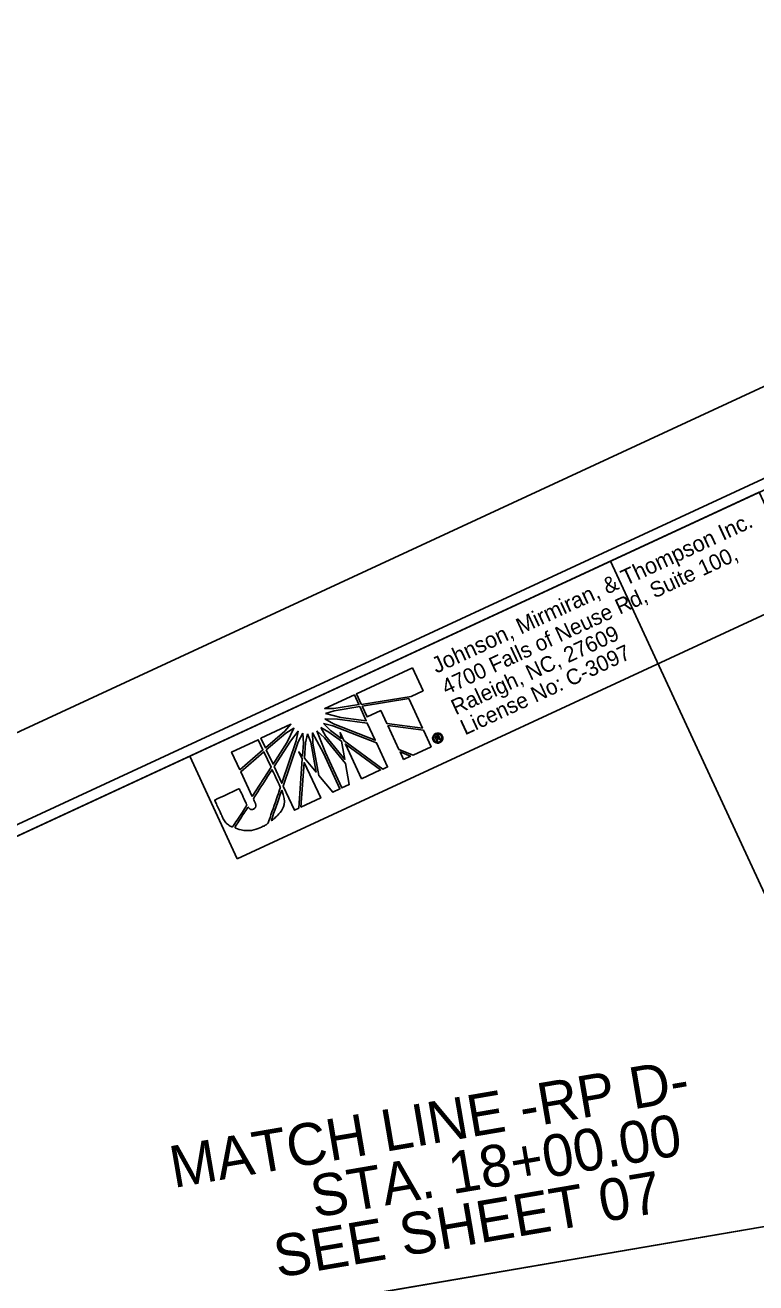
# Model space of a CAD drawing. Extents: x 1722892 to 1724880, y 971019 to 972720.
# Drawn here: x 1724056.8 to 1724231.4, y 972419.6 to 972720.2 of the extents above; entities that cross this region are included whole.
import ezdxf

# ---------------------------------------------------------------- set-up
doc = ezdxf.new("R2010")
doc.units = 0
for name, color, linetype in [('Matchline', 7, 'Continuous'), ('Matchline Text', 7, 'Continuous'), ('Prop Dimension Text', 7, 'Continuous'), ('Sheet Clip Boundary CELL', 7, 'Continuous'), ('Sheet Layout Plan Border', 7, 'Continuous'), ('Sheet Plan CELL', 7, 'Continuous'), ('Sheet Plot Border Inside CELL', 7, 'Continuous'), ('Sheet Plot Border Outside CELL', 7, 'Continuous')]:
    doc.layers.add(name, color=color, linetype=linetype)

msp = doc.modelspace()

# ---------------------------------------------------------------- linework, layer by layer
at = {"layer": 'Matchline'}
msp.add_line((1724068.11, 972404.72), (1724340.27, 972451.29), dxfattribs=at)
at = {"layer": 'Prop Dimension Text'}
for p, q in [((1724149.33, 972566.59), (1724135.95, 972560.37)), ((1724151.88, 972561.11), (1724149.33, 972566.59)), ((1724135.47, 972560.11), (1724128.39, 972556.86)), ((1724136.53, 972557.82), (1724135.47, 972560.11)), ((1724135.95, 972560.37), (1724137.09, 972557.91)), ((1724137.12, 972557.84), (1724149.04, 972559.78)), ((1724148.47, 972559.23), (1724137.3, 972557.46)), ((1724151.74, 972552.2), (1724148.47, 972559.23)), ((1724149.04, 972559.78), (1724151.88, 972561.11)), ((1724128.39, 972556.86), (1724130.57, 972556.85)), ((1724130.61, 972556.31), (1724128.53, 972555.64)), ((1724128.53, 972555.64), (1724132.21, 972554.7)), ((1724130.57, 972556.85), (1724136.53, 972557.82)), ((1724136.76, 972557.34), (1724130.61, 972556.31)), ((1724138.28, 972553.94), (1724136.76, 972557.34)), ((1724137.09, 972557.91), (1724137.12, 972557.84)), ((1724137.3, 972557.46), (1724137.32, 972557.42)), ((1724137.32, 972557.42), (1724138.51, 972554.85)), ((1724138.51, 972554.85), (1724141.78, 972556.37)), ((1724141.78, 972556.37), (1724143.2, 972553.32)), ((1724120.28, 972553.09), (1724113.12, 972549.76)), ((1724118.83, 972551.43), (1724120.28, 972553.09)), ((1724128.04, 972553.28), (1724129.76, 972551.61)), ((1724130.33, 972552.77), (1724128.04, 972553.28)), ((1724128.43, 972554.4), (1724130.47, 972553.21)), ((1724131.46, 972554.31), (1724128.43, 972554.4)), ((1724140.75, 972548.64), (1724130.33, 972552.77)), ((1724130.47, 972553.21), (1724140.44, 972549.3)), ((1724138.55, 972553.38), (1724131.46, 972554.31)), ((1724132.21, 972554.7), (1724138.28, 972553.94)), ((1724140.44, 972549.3), (1724138.55, 972553.38)), ((1724143.2, 972553.32), (1724151.74, 972552.2)), ((1724143.44, 972552.79), (1724146.09, 972547.1)), ((1724151.97, 972551.71), (1724143.44, 972552.79)), ((1724112.47, 972549.42), (1724106.1, 972546.47)), ((1724113.61, 972546.97), (1724112.47, 972549.42)), ((1724113.12, 972549.76), (1724114.18, 972547.48)), ((1724114.18, 972547.48), (1724118.83, 972551.43)), ((1724119.06, 972550.94), (1724114.41, 972546.99)), ((1724121.02, 972552.16), (1724119.06, 972550.94)), ((1724119.38, 972548.79), (1724121.02, 972552.16)), ((1724122.01, 972551.42), (1724120.15, 972549.06)), ((1724121.58, 972549.12), (1724122.01, 972551.42)), ((1724123.1, 972550.99), (1724122.01, 972548.9)), ((1724123.27, 972548.59), (1724123.1, 972550.99)), ((1724124.28, 972550.85), (1724123.77, 972548.64)), ((1724125.01, 972548.8), (1724124.28, 972550.85)), ((1724128.07, 972546.16), (1724125.46, 972551.05)), ((1724125.46, 972551.05), (1724125.53, 972548.61)), ((1724126.51, 972551.54), (1724128.52, 972546.37)), ((1724128.3, 972549.89), (1724126.51, 972551.54)), ((1724127.4, 972552.3), (1724128.55, 972550.36)), ((1724129.38, 972551.25), (1724127.4, 972552.3)), ((1724133.37, 972543.75), (1724128.3, 972549.89)), ((1724128.55, 972550.36), (1724133.19, 972544.69)), ((1724132.41, 972549.03), (1724129.38, 972551.25)), ((1724129.76, 972551.61), (1724132.3, 972549.71)), ((1724132.3, 972549.71), (1724132.04, 972551.12)), ((1724132.04, 972551.12), (1724132.91, 972549.26)), ((1724153.81, 972547.75), (1724151.97, 972551.71)), ((1724154.75, 972550.11), (1724155.15, 972550.29)), ((1724155.2, 972549.13), (1724154.75, 972550.11)), ((1724154.88, 972550.87), (1724154.98, 972550.66)), ((1724154.98, 972550.66), (1724154.88, 972550.87)), ((1724155.24, 972550.11), (1724155.06, 972550.03)), ((1724155.06, 972550.03), (1724155.17, 972549.8)), ((1724155.15, 972550.29), (1724155.21, 972550.32)), ((1724155.15, 972550.29), (1724155.24, 972550.11)), ((1724155.24, 972550.11), (1724155.15, 972550.29)), ((1724155.17, 972549.8), (1724155.34, 972549.88)), ((1724155.26, 972550.12), (1724155.24, 972550.11)), ((1724155.42, 972549.7), (1724155.25, 972549.62)), ((1724155.25, 972549.62), (1724155.42, 972549.24)), ((1724155.34, 972549.88), (1724155.42, 972549.7)), ((1724155.42, 972549.7), (1724155.34, 972549.88)), ((1724155.34, 972549.88), (1724155.35, 972549.88)), ((1724155.43, 972549.7), (1724155.42, 972549.7)), ((1724106.1, 972546.47), (1724108.06, 972542.24)), ((1724108.06, 972542.24), (1724113.61, 972546.97)), ((1724113.83, 972546.5), (1724108.29, 972541.76)), ((1724115.54, 972542.82), (1724113.83, 972546.5)), ((1724114.41, 972546.99), (1724116.01, 972543.54)), ((1724116.01, 972543.54), (1724119.38, 972548.79)), ((1724120.15, 972549.06), (1724116.27, 972542.99)), ((1724118.11, 972539.01), (1724121.58, 972549.12)), ((1724122.01, 972548.9), (1724118.42, 972538.34)), ((1724122.99, 972544.87), (1724122.21, 972546.55)), ((1724122.21, 972546.55), (1724123.06, 972545.54)), ((1724123.06, 972545.54), (1724123.27, 972548.59)), ((1724123.77, 972548.64), (1724123.52, 972545.03)), ((1724126.31, 972541.68), (1724125.01, 972548.8)), ((1724125.53, 972548.61), (1724126.93, 972540.89)), ((1724133.19, 972544.69), (1724132.41, 972549.03)), ((1724132.91, 972549.26), (1724142.28, 972542.4)), ((1724141.74, 972542.19), (1724133.33, 972548.35)), ((1724133.33, 972548.35), (1724137.18, 972540.07)), ((1724143.4, 972542.92), (1724140.75, 972548.64)), ((1724146.09, 972547.1), (1724149.49, 972545.75)), ((1724148.86, 972545.46), (1724146.38, 972546.48)), ((1724146.38, 972546.48), (1724147.21, 972544.69)), ((1724149.49, 972545.75), (1724153.81, 972547.75)), ((1724155.42, 972549.24), (1724155.2, 972549.13)), ((1724155.78, 972548.94), (1724155.88, 972548.73)), ((1724155.88, 972548.73), (1724155.78, 972548.94)), ((1724155.78, 972548.94), (1724155.79, 972548.94)), ((1724155.89, 972548.73), (1724155.88, 972548.73)), ((1724122.16, 972533.05), (1724122.99, 972544.87)), ((1724123.42, 972543.96), (1724122.65, 972533.28)), ((1724127.4, 972535.49), (1724123.42, 972543.96)), ((1724123.52, 972545.03), (1724126.31, 972541.68)), ((1724132.01, 972537.67), (1724128.07, 972546.16)), ((1724128.52, 972546.37), (1724132.46, 972537.88)), ((1724134.23, 972538.7), (1724133.37, 972543.75)), ((1724147.21, 972544.69), (1724148.86, 972545.46)), ((1724108.29, 972541.76), (1724111.05, 972535.82)), ((1724111.05, 972535.82), (1724115.54, 972542.82)), ((1724116.27, 972542.99), (1724118.11, 972539.01)), ((1724126.93, 972540.89), (1724130.27, 972536.86)), ((1724137.18, 972540.07), (1724141.74, 972542.19)), ((1724142.28, 972542.4), (1724143.4, 972542.92)), ((1724118.42, 972538.34), (1724121.11, 972532.56)), ((1724130.27, 972536.86), (1724132.01, 972537.67)), ((1724132.46, 972537.88), (1724134.23, 972538.7)), ((1724122.65, 972533.28), (1724127.4, 972535.49)), ((1724121.11, 972532.56), (1724122.16, 972533.05))]:
    msp.add_line(p, q, dxfattribs=at)
msp.add_lwpolyline([(1724107.47, 972520.92), (1724243.59, 972584.01), (1724232.21, 972608.57), (1724096.09, 972545.49)], close=True, dxfattribs=at)
for points in [[(1724149.33, 972566.59), (1724135.95, 972560.37), (1724137.09, 972557.91), (1724137.12, 972557.84), (1724149.04, 972559.78), (1724151.88, 972561.11), (1724149.33, 972566.59)], [(1724130.57, 972556.85), (1724136.53, 972557.82), (1724135.47, 972560.11), (1724128.39, 972556.86), (1724130.57, 972556.85)], [(1724137.3, 972557.46), (1724137.32, 972557.42), (1724138.51, 972554.85), (1724141.78, 972556.37), (1724143.2, 972553.32), (1724151.74, 972552.2), (1724148.47, 972559.23), (1724137.3, 972557.46)], [(1724128.53, 972555.64), (1724132.21, 972554.7), (1724138.28, 972553.94), (1724136.76, 972557.34), (1724130.61, 972556.31), (1724128.53, 972555.64)], [(1724118.83, 972551.43), (1724120.28, 972553.09), (1724113.12, 972549.76), (1724114.18, 972547.48), (1724118.83, 972551.43)], [(1724128.04, 972553.28), (1724129.76, 972551.61), (1724132.3, 972549.71), (1724132.04, 972551.12), (1724132.91, 972549.26), (1724142.28, 972542.4), (1724143.4, 972542.92), (1724140.75, 972548.64), (1724130.33, 972552.77), (1724128.04, 972553.28)], [(1724128.43, 972554.4), (1724130.47, 972553.21), (1724140.44, 972549.3), (1724138.55, 972553.38), (1724131.46, 972554.31), (1724128.43, 972554.4)], [(1724143.44, 972552.79), (1724146.09, 972547.1), (1724149.49, 972545.75), (1724153.81, 972547.75), (1724151.97, 972551.71), (1724143.44, 972552.79), (1724143.44, 972552.79)], [(1724108.06, 972542.24), (1724113.61, 972546.97), (1724112.47, 972549.42), (1724106.1, 972546.47), (1724108.06, 972542.24)], [(1724114.41, 972546.99), (1724116.01, 972543.54), (1724119.38, 972548.79), (1724121.02, 972552.16), (1724119.06, 972550.94), (1724114.41, 972546.99)], [(1724116.27, 972542.99), (1724118.11, 972539.01), (1724121.58, 972549.12), (1724122.01, 972551.42), (1724120.15, 972549.06), (1724116.27, 972542.99)], [(1724123.1, 972550.99), (1724122.01, 972548.9), (1724118.42, 972538.34), (1724121.11, 972532.56), (1724122.16, 972533.05), (1724122.99, 972544.87), (1724122.21, 972546.55), (1724123.06, 972545.54), (1724123.27, 972548.59), (1724123.1, 972550.99)], [(1724124.28, 972550.85), (1724123.77, 972548.64), (1724123.52, 972545.03), (1724126.31, 972541.68), (1724125.01, 972548.8), (1724124.28, 972550.85)], [(1724125.53, 972548.61), (1724126.93, 972540.89), (1724130.27, 972536.86), (1724132.01, 972537.67), (1724128.07, 972546.16), (1724125.46, 972551.05), (1724125.53, 972548.61)], [(1724126.51, 972551.54), (1724128.52, 972546.37), (1724132.46, 972537.88), (1724134.23, 972538.7), (1724133.37, 972543.75), (1724128.3, 972549.89), (1724126.51, 972551.54)], [(1724127.4, 972552.3), (1724128.55, 972550.36), (1724133.19, 972544.69), (1724132.41, 972549.03), (1724129.38, 972551.25), (1724127.4, 972552.3)], [(1724155.92, 972549.75), (1724155.94, 972549.69), (1724155.97, 972549.66), (1724155.99, 972549.63), (1724156.06, 972549.53), (1724155.86, 972549.44)], [(1724111.05, 972535.82), (1724115.54, 972542.82), (1724113.83, 972546.5), (1724108.29, 972541.76), (1724111.05, 972535.82)], [(1724137.18, 972540.07), (1724141.74, 972542.19), (1724133.33, 972548.35), (1724137.18, 972540.07)], [(1724147.21, 972544.69), (1724147.21, 972544.69), (1724148.86, 972545.46), (1724146.38, 972546.48), (1724147.21, 972544.69)], [(1724122.65, 972533.28), (1724127.4, 972535.49), (1724123.42, 972543.96), (1724122.65, 972533.28)]]:
    msp.add_lwpolyline(points, dxfattribs=at)
for points, degree in [([(1724155.88, 972548.73), (1724155.58, 972548.59), (1724155.28, 972548.58), (1724154.97, 972548.69), (1724154.66, 972548.8), (1724154.44, 972549), (1724154.3, 972549.31), (1724154.16, 972549.61), (1724154.14, 972549.91), (1724154.26, 972550.21), (1724154.38, 972550.51), (1724154.58, 972550.73), (1724154.88, 972550.87)], 3), ([(1724154.98, 972550.66), (1724154.74, 972550.55), (1724154.57, 972550.38), (1724154.48, 972550.14), (1724154.39, 972549.9), (1724154.4, 972549.64), (1724154.51, 972549.4), (1724154.62, 972549.16), (1724154.81, 972548.99), (1724155.05, 972548.9), (1724155.3, 972548.81), (1724155.54, 972548.83), (1724155.78, 972548.94)], 3), ([(1724154.88, 972550.87), (1724155.18, 972551.01), (1724155.49, 972551.02), (1724155.8, 972550.92), (1724156.1, 972550.82), (1724156.32, 972550.61), (1724156.46, 972550.31)], 3), ([(1724155.79, 972548.94), (1724156.03, 972549.05), (1724156.19, 972549.23), (1724156.28, 972549.48), (1724156.37, 972549.72), (1724156.36, 972549.97), (1724156.25, 972550.21), (1724156.14, 972550.45), (1724155.95, 972550.62), (1724155.71, 972550.71), (1724155.46, 972550.79), (1724155.22, 972550.78), (1724154.98, 972550.66)], 3), ([(1724155.21, 972550.32), (1724155.46, 972550.44), (1724155.63, 972550.4), (1724155.72, 972550.2), (1724155.76, 972550.11), (1724155.76, 972550.03), (1724155.7, 972549.94)], 3), ([(1724155.35, 972549.88), (1724155.49, 972549.95), (1724155.54, 972550.02), (1724155.51, 972550.1), (1724155.47, 972550.17), (1724155.39, 972550.18), (1724155.26, 972550.12)], 3), ([(1724155.62, 972549.75), (1724155.58, 972549.75), (1724155.52, 972549.75), (1724155.43, 972549.7)], 2), ([(1724155.86, 972549.44), (1724155.81, 972549.48), (1724155.76, 972549.52), (1724155.73, 972549.6), (1724155.69, 972549.68), (1724155.66, 972549.73), (1724155.62, 972549.75)], 3), ([(1724155.7, 972549.94), (1724155.78, 972549.93), (1724155.85, 972549.87), (1724155.92, 972549.75)], 2), ([(1724156.46, 972550.31), (1724156.6, 972550.01), (1724156.62, 972549.71), (1724156.51, 972549.4), (1724156.39, 972549.1), (1724156.19, 972548.87), (1724155.89, 972548.73)], 3), ([(1724111.33, 972532.82), (1724110.95, 972532.65), (1724110.53, 972532.71), (1724110.06, 972533.35), (1724110.06, 972533.35), (1724106.81, 972528.4), (1724106.81, 972528.4), (1724108.9, 972527.57), (1724111.56, 972527.73), (1724113.46, 972528.62), (1724113.96, 972528.84), (1724114.32, 972529.06), (1724114.79, 972529.41), (1724114.79, 972529.41), (1724117.78, 972538), (1724117.78, 972538), (1724117.78, 972538), (1724115.78, 972542.29), (1724115.78, 972542.29), (1724115.78, 972542.29), (1724111.3, 972535.29), (1724111.3, 972535.29), (1724112.04, 972533.68), (1724111.85, 972533.07), (1724111.33, 972532.82)], 3), ([(1724111.33, 972532.82), (1724110.95, 972532.65), (1724110.53, 972532.71), (1724110.06, 972533.35), (1724110.06, 972533.35), (1724106.81, 972528.4), (1724106.81, 972528.4), (1724108.9, 972527.57), (1724111.56, 972527.73), (1724113.46, 972528.62), (1724113.96, 972528.84), (1724114.32, 972529.06), (1724114.79, 972529.41), (1724114.79, 972529.41), (1724117.78, 972538), (1724117.78, 972538), (1724117.78, 972538), (1724115.78, 972542.29), (1724115.78, 972542.29), (1724115.78, 972542.29), (1724111.3, 972535.29), (1724111.3, 972535.29), (1724112.04, 972533.68), (1724111.85, 972533.07), (1724111.33, 972532.82)], 3), ([(1724107.95, 972537.7), (1724107.95, 972537.7), (1724102.06, 972534.97), (1724102.06, 972534.97), (1724102.06, 972534.97), (1724103.77, 972531.28), (1724103.77, 972531.28), (1724103.77, 972531.28), (1724103.95, 972530.89), (1724103.95, 972530.89), (1724104.49, 972529.73), (1724105.29, 972529), (1724106.32, 972528.54), (1724106.32, 972528.54), (1724109.8, 972533.73), (1724109.76, 972533.81), (1724109.76, 972533.81), (1724107.95, 972537.7), (1724107.95, 972537.7)], 3), ([(1724118.09, 972537.33), (1724118.09, 972537.33), (1724115.51, 972529.91), (1724115.51, 972529.91), (1724117.66, 972531.64), (1724119.32, 972534.37), (1724118.09, 972537.33)], 3)]:
    msp.add_open_spline(points, degree=degree, dxfattribs=at)
at = {"layer": 'Sheet Clip Boundary CELL'}
msp.add_lwpolyline([(1723539.64, 971130.3), (1724809.87, 971718.99), (1724457.28, 972479.77), (1724285.57, 972400.19), (1724196.64, 972592.07), (1723098.13, 972082.96)], close=True, dxfattribs=at)
at = {"layer": 'Sheet Layout Plan Border'}
for points in [[(1724374.31, 972628.66), (1724393.21, 972460.35), (1724068.11, 972404.72), (1724049.69, 972271.07), (1723832.27, 972270.2), (1723815.72, 972244.69), (1723599.72, 972315.43), (1723098.13, 972082.96), (1723600.74, 971158.62), (1723483.33, 971374.55), (1723802.12, 971464.67), (1724031.92, 971474.7), (1724072.16, 971562.21), (1724326.28, 971494.87), (1724493, 971572.14)], [(1724391.63, 972460.07), (1724068.11, 972404.72), (1724049.69, 972271.07), (1723832.27, 972270.2), (1723815.72, 972244.69), (1723599.72, 972315.43), (1723098.13, 972082.96), (1723600.74, 971158.62), (1723483.33, 971374.55), (1723802.12, 971464.67), (1724031.92, 971474.7), (1724072.16, 971562.21), (1724326.28, 971494.87), (1724488.18, 971569.9)]]:
    msp.add_lwpolyline(points, close=True, dxfattribs=at)
at = {"layer": 'Sheet Plan CELL'}
msp.add_lwpolyline([(1724413.74, 972692.69), (1723052.76, 972061.94), (1723494.28, 971109.28), (1724855.24, 971740.02)], close=True, dxfattribs=at)
at = {"layer": 'Sheet Plot Border Inside CELL'}
msp.add_lwpolyline([(1723356.08, 971042.46), (1724867.62, 971743), (1724424.02, 972700.19), (1722912.46, 971999.66)], close=True, dxfattribs=at)
at = {"layer": 'Sheet Plot Border Outside CELL'}
msp.add_lwpolyline([(1723352.69, 971018.84), (1724880.13, 971726.74), (1724419.69, 972720.23), (1722892.25, 972012.33)], close=True, dxfattribs=at)

# ---------------------------------------------------------------- texts
at = {"layer": 'Matchline Text'}
for s, p in [('MATCH LINE -RP D-', (1724092.27, 972442.23)), ('STA. 18+00.00', (1724125.94, 972435.13)), ('SEE SHEET 07', (1724117.14, 972420.77))]:
    msp.add_text(s, height=10, rotation=9.7085, dxfattribs=at).set_placement(p)
at = {"layer": 'Prop Dimension Text'}
for s, height, p in [('Johnson, Mirmiran, & Thompson Inc.', 3.8334, (1724155.06, 972565.18)), ('4700 Falls of Neuse Rd, Suite 100, ', 3.7239, (1724157.43, 972560.07)), ('Raleigh, NC, 27609', 3.7239, (1724159.67, 972555.24)), ('License No: C-3097', 3.7239, (1724161.9, 972550.42))]:
    msp.add_text(s, height=height, rotation=24.8656, dxfattribs=at).set_placement(p)

doc.saveas('drawing.dxf')
